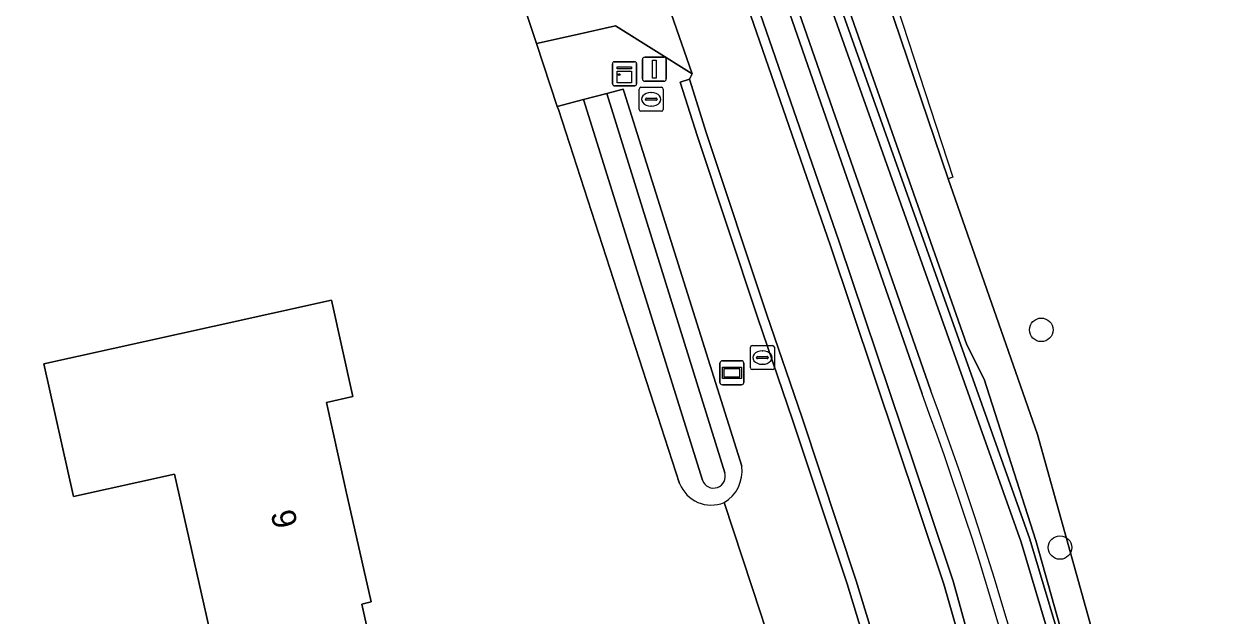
# Model space of a CAD drawing. Extents: x 162510 to 163918, y 388494 to 389774.
# Drawn here: x 163268.7 to 163318.9, y 389108.3 to 389132.9 of the extents above; entities that cross this region are included whole.
import ezdxf

# ---------------------------------------------------------------- set-up
doc = ezdxf.new("R2010")
doc.units = 0
for name, color, linetype in [('IMGEO_Afsluitpaal', 7, 'Continuous'), ('IMGEO_Boom', 7, 'Continuous'), ('IMGEO_Brandkraan', 7, 'Continuous'), ('IMGEO_Erf', 7, 'Continuous'), ('IMGEO_Grasland_agrarisch', 7, 'Continuous'), ('IMGEO_Grasland_overig', 7, 'Continuous'), ('IMGEO_Groenvoorziening', 7, 'Continuous'), ('IMGEO_Hek', 7, 'Continuous'), ('IMGEO_Kast', 7, 'Continuous'), ('IMGEO_Loofbos', 7, 'Continuous'), ('IMGEO_Oever', 7, 'Continuous'), ('IMGEO_Pand', 7, 'Continuous'), ('IMGEO_Pand_nummerreeks', 7, 'Continuous'), ('IMGEO_Rijbaan_lokaal_gesloten', 7, 'Continuous'), ('IMGEO_Rijbaan_lokaal_halfverhard', 7, 'Continuous'), ('IMGEO_Rijbaan_lokaal_open', 7, 'Continuous'), ('IMGEO_Rioolput', 7, 'Continuous'), ('IMGEO_Verklikker', 7, 'Continuous'), ('IMGEO_Waterloop', 7, 'Continuous')]:
    doc.layers.add(name, color=color, linetype=linetype)

msp = doc.modelspace()

# ---------------------------------------------------------------- linework, layer by layer
at = {"layer": 'IMGEO_Afsluitpaal'}
for p, q in [((163294.442, 389130.657), (163294.442, 389131.457)), ((163294.442, 389131.457), (163294.442, 389130.657)), ((163294.542, 389131.557), (163295.332, 389131.557)), ((163295.332, 389131.557), (163294.542, 389131.557)), ((163295.432, 389131.457), (163295.432, 389130.657)), ((163295.432, 389130.657), (163295.432, 389131.457)), ((163295.332, 389130.557), (163294.542, 389130.557)), ((163294.542, 389130.557), (163295.332, 389130.557))]:
    msp.add_line(p, q, dxfattribs=at)
msp.add_lwpolyline([(163294.862, 389131.432), (163295.012, 389131.432), (163295.012, 389130.682), (163294.862, 389130.682), (163294.862, 389131.432)], dxfattribs=at)
for centre, start, end in [((163294.542, 389131.457), 90, 180), ((163294.542, 389131.457), 90, 180), ((163295.332, 389131.457), 0, 90), ((163295.332, 389131.457), 360, 90), ((163294.542, 389130.657), 180, 270), ((163294.542, 389130.657), 180, 270), ((163295.332, 389130.657), 270, 0), ((163295.332, 389130.657), 270, 0)]:
    msp.add_arc(centre, 0.1, start, end, dxfattribs=at)
at = {"layer": 'IMGEO_Boom'}
for centre in [(163311.036, 389120.214), (163311.815, 389111.157)]:
    msp.add_circle(centre, 0.489, dxfattribs=at)
at = {"layer": 'IMGEO_Brandkraan'}
for p, q in [((163298.932, 389118.636), (163298.932, 389119.488)), ((163299.007, 389119.562), (163299.859, 389119.562)), ((163299.234, 389119.105), (163299.632, 389119.105)), ((163299.42, 389119.342), (163299.445, 389119.342)), ((163299.933, 389119.488), (163299.933, 389118.636)), ((163299.191, 389119.056), (163299.191, 389119.068)), ((163299.629, 389119.019), (163299.231, 389119.019)), ((163299.443, 389118.782), (163299.418, 389118.782)), ((163299.675, 389119.068), (163299.675, 389119.056)), ((163299.859, 389118.562), (163299.007, 389118.562))]:
    msp.add_line(p, q, dxfattribs=at)
for points in [[(163298.932, 389118.636), (163298.932, 389119.488)], [(163299.007, 389119.562), (163299.859, 389119.562)], [(163299.933, 389119.488), (163299.933, 389118.636)], [(163299.859, 389118.562), (163299.007, 389118.562)]]:
    msp.add_lwpolyline(points, dxfattribs=at)
for centre, radius, start, end in [((163299.009, 389119.486), 0.0765, 91.552, 178.448), ((163299.009, 389119.486), 0.0765, 91.552, 178.448), ((163299.231, 389119.065), 0.0403, 85.8775, 175.7526), ((163299.636, 389119.067), 0.0386, 1.7309, 96.639), ((163299.857, 389119.486), 0.0765, 1.552, 88.448), ((163299.857, 389119.486), 0.0765, 1.552, 88.448), ((163299.009, 389118.638), 0.0765, 181.552, 268.448), ((163299.009, 389118.638), 0.0765, 181.552, 268.448), ((163299.228, 389119.055), 0.0366, 178.938, 274.7102), ((163299.632, 389119.062), 0.043, 264.8664, 352.4533), ((163299.857, 389118.638), 0.0765, 271.552, 358.448), ((163299.857, 389118.638), 0.0765, 271.552, 358.448)]:
    msp.add_arc(centre, radius, start, end, dxfattribs=at)
for centre, major_axis, ratio, start_param, end_param in [((163299.419, 389119.062), (-0.387, 0.002), 0.722429, 4.712389, 7.853982), ((163299.444, 389119.062), (-0.39, 0.002), 0.717154, 1.570796, 4.712389)]:
    msp.add_ellipse(centre, major_axis=major_axis, ratio=ratio, start_param=start_param, end_param=end_param, dxfattribs=at)
at = {"layer": 'IMGEO_Erf'}
msp.add_lwpolyline([(163295.99, 389113.816), (163290.943, 389129.375), (163290.899, 389129.508), (163290.029, 389132.125), (163288.773, 389135.907), (163287.617, 389139.385), (163285.544, 389145.627), (163261.78, 389139.826), (163241.096, 389135.563), (163217.196, 389130.559), (163224.258, 389085.897), (163224.403, 389084.979), (163231.973, 389086.773), (163247.896, 389090.8), (163281.65, 389099.338), (163299.098, 389104.325), (163298.18, 389106.706), (163299.751, 389107.167), (163299.514, 389107.922), (163299.362, 389108.405), (163297.837, 389113.028)], dxfattribs=at)
msp.add_lwpolyline([(163269.539, 389118.803), (163276.624, 389120.373), (163281.505, 389121.454), (163282.389, 389117.439), (163281.296, 389117.198), (163282.056, 389113.745), (163282.1, 389113.551), (163283.16, 389108.904), (163282.762, 389108.795), (163282.963, 389107.934), (163278.843, 389107.021), (163278.657, 389107.864), (163276.508, 389107.388), (163274.968, 389114.211), (163270.766, 389113.282)], close=True, dxfattribs=at)
msp.add_arc((163297.304, 389114.337), 1.413, 201.6231, 292.1671, dxfattribs=at)
at = {"layer": 'IMGEO_Grasland_agrarisch'}
for points in [[(163307.161, 389126.5), (163310.878, 389115.861), (163314.091, 389104.329), (163316.991, 389092.126), (163318.506, 389073.312), (163367.516, 389078.302), (163374.787, 389079.284), (163366.654, 389123.96), (163359.915, 389160.853), (163356.398, 389163.04), (163342.099, 389172.967), (163307.356, 389168.666), (163293.477, 389168.592), (163298.963, 389150.69)], [(163359.915, 389160.853), (163356.398, 389163.04), (163342.099, 389172.967), (163307.356, 389168.666), (163293.81, 389168.694), (163295.529, 389162.768), (163307.351, 389126.562), (163307.161, 389126.5), (163310.878, 389115.861), (163314.091, 389104.329), (163316.991, 389092.126), (163318.506, 389073.312), (163367.516, 389078.302), (163374.787, 389079.284), (163366.654, 389123.96)]]:
    msp.add_lwpolyline(points, close=True, dxfattribs=at)
at = {"layer": 'IMGEO_Grasland_overig'}
for points in [[(163269.586, 389223.92), (163270.524, 389220.606), (163272.482, 389214.36), (163274.556, 389207.832), (163276.596, 389201.21), (163279.233, 389192.779), (163282.821, 389181.85), (163285.014, 389175.274), (163289.738, 389161.323), (163294.443, 389147.5), (163296.944, 389140.288), (163298.713, 389135.186), (163302.632, 389123.878), (163306.31, 389112.906), (163307.368, 389109.754), (163307.917, 389107.807), (163308.741, 389104.905), (163309.765, 389101.198)], [(163380.603, 389076.405), (163382.808, 389076.715), (163383.644, 389076.959), (163385.385, 389077.656), (163386.687, 389078.319), (163386.481, 389080.864), (163374.787, 389079.284), (163367.516, 389078.302), (163318.506, 389073.312), (163316.991, 389092.126), (163314.091, 389104.329), (163310.878, 389115.861), (163307.161, 389126.5), (163298.963, 389150.69), (163293.477, 389168.592), (163291.787, 389174.109), (163289.599, 389172.956)], [(163289.599, 389172.956), (163289.702, 389172.575), (163290.669, 389168.7), (163291.377, 389166.688), (163307.934, 389119.584), (163308.654, 389118.16), (163310.816, 389111.455), (163312.329, 389106.026), (163313.789, 389100.576), (163315.665, 389092.463), (163317.148, 389071.288), (163317.163, 389071.036), (163328.39, 389071.628), (163350.586, 389073.126), (163366.024, 389074.655), (163372.103, 389075.6), (163375.233, 389076.384), (163378.482, 389077.444), (163380.722, 389078.49), (163381.482, 389078.62), (163381.768, 389078.515), (163381.923, 389078.247), (163381.855, 389077.888)], [(163306.075, 389117.546), (163291.361, 389159.819)]]:
    msp.add_lwpolyline(points, dxfattribs=at)
msp.add_arc((163166.83, 389065.927), 148.505, 9.06284, 20.34014, dxfattribs=at)
at = {"layer": 'IMGEO_Groenvoorziening'}
msp.add_lwpolyline([(163289.599, 389172.956), (163288.407, 389172.464), (163292.024, 389161.132), (163292.522, 389161.166), (163292.978, 389160.963), (163310.563, 389111.499), (163312.208, 389105.99), (163312.329, 389106.026), (163310.816, 389111.455), (163308.654, 389118.16), (163307.934, 389119.584), (163291.377, 389166.688), (163290.669, 389168.7), (163289.702, 389172.575)], close=True, dxfattribs=at)
at = {"layer": 'IMGEO_Hek'}
for points in [[(163291.787, 389174.109), (163293.477, 389168.592), (163298.963, 389150.69), (163307.161, 389126.5)], [(163386.481, 389080.864), (163374.787, 389079.284), (163367.516, 389078.302), (163318.506, 389073.312), (163316.991, 389092.126), (163314.091, 389104.329), (163310.878, 389115.861), (163307.161, 389126.5)]]:
    msp.add_lwpolyline(points, dxfattribs=at)
at = {"layer": 'IMGEO_Kast'}
for p, q in [((163293.197, 389130.442), (163293.197, 389131.283)), ((163293.197, 389131.283), (163293.197, 389130.442)), ((163293.272, 389131.367), (163294.113, 389131.367)), ((163294.113, 389131.367), (163293.272, 389131.367)), ((163294.197, 389131.292), (163294.197, 389130.451)), ((163294.197, 389130.451), (163294.197, 389131.292)), ((163294.122, 389130.367), (163293.281, 389130.367)), ((163293.281, 389130.367), (163294.122, 389130.367))]:
    msp.add_line(p, q, dxfattribs=at)
for points in [[(163293.392, 389131.157), (163293.992, 389131.157), (163293.992, 389131.072), (163293.392, 389131.072), (163293.392, 389131.157)], [(163293.392, 389130.982), (163293.992, 389130.982), (163293.992, 389130.493), (163293.392, 389130.493), (163293.392, 389130.982)]]:
    msp.add_lwpolyline(points, dxfattribs=at)
msp.add_circle((163293.476, 389130.831), 0.0377, dxfattribs=at)
for centre, start, end in [((163293.275, 389131.289), 92.4484, 184.2845), ((163293.275, 389131.289), 92.4484, 184.2845), ((163294.119, 389131.289), 2.4484, 94.2845), ((163294.119, 389131.289), 2.4484, 94.2845), ((163293.275, 389130.445), 182.4484, 274.2845), ((163293.275, 389130.445), 182.4484, 274.2845), ((163294.119, 389130.445), 272.4484, 4.2845), ((163294.119, 389130.445), 272.4484, 4.2845)]:
    msp.add_arc(centre, 0.0779, start, end, dxfattribs=at)
at = {"layer": 'IMGEO_Loofbos'}
for points in [[(163304.458, 389104.718), (163302.957, 389109.643), (163300.704, 389116.431), (163299.226, 389120.745), (163296.729, 389128.263), (163296.018, 389130.522), (163296.4, 389130.642), (163296.508, 389130.868), (163293.321, 389132.857), (163291.728, 389132.494), (163290.029, 389132.125), (163290.899, 389129.508), (163291.995, 389129.793), (163292.964, 389130.045), (163293.639, 389130.221), (163293.675, 389130.106), (163298.577, 389114.536)], [(163297.837, 389113.028), (163299.362, 389108.405), (163299.514, 389107.922), (163299.751, 389107.167), (163299.799, 389107.183), (163299.874, 389107.207), (163300.332, 389107.355), (163301.202, 389107.649), (163302.376, 389104.587), (163303.586, 389100.712), (163305.385, 389094.695), (163306.866, 389087.58), (163307.505, 389083.14), (163307.628, 389080.974), (163307.534, 389078.67), (163306.948, 389074.273), (163306.179, 389070.481), (163304.839, 389066.018), (163303.89, 389063.876), (163301.226, 389059.667), (163296.877, 389054.754), (163292.823, 389050.667), (163286.398, 389045.174), (163271.935, 389034.148)]]:
    msp.add_lwpolyline(points, dxfattribs=at)
msp.add_arc((163297.053, 389114.348), 1.536, 300.7033, 7.0208, dxfattribs=at)
at = {"layer": 'IMGEO_Oever'}
for points in [[(163312.208, 389105.99), (163310.563, 389111.499), (163292.978, 389160.963)], [(163292.669, 389160.677), (163310.195, 389111.379), (163311.834, 389105.891)], [(163291.361, 389159.819), (163306.075, 389117.546)], [(163306.442, 389117.671), (163291.732, 389159.93)], [(163293.675, 389130.106), (163293.639, 389130.221), (163292.964, 389130.045), (163297.867, 389114.272)], [(163296.943, 389113.959), (163291.995, 389129.793), (163290.899, 389129.508), (163290.943, 389129.375), (163295.99, 389113.816)], [(163298.577, 389114.536), (163293.675, 389130.106)]]:
    msp.add_lwpolyline(points, dxfattribs=at)
for centre, radius, start, end in [((163166.761, 389065.905), 148.965, 9.06066, 20.33478), ((163166.83, 389065.927), 148.505, 9.06284, 20.34014), ((163297.404, 389114.119), 0.488, 199.0918, 18.3353), ((163297.053, 389114.348), 1.536, 300.7033, 7.0208), ((163297.304, 389114.337), 1.413, 201.6231, 292.1671)]:
    msp.add_arc(centre, radius, start, end, dxfattribs=at)
at = {"layer": 'IMGEO_Pand'}
msp.add_lwpolyline([(163282.389, 389117.439), (163281.505, 389121.454), (163276.624, 389120.373), (163269.539, 389118.803), (163270.766, 389113.282), (163274.968, 389114.211), (163276.508, 389107.388), (163278.657, 389107.864), (163278.843, 389107.021), (163282.963, 389107.934), (163282.762, 389108.795), (163283.16, 389108.904), (163282.1, 389113.551), (163282.056, 389113.745), (163281.296, 389117.198)], close=True, dxfattribs=at)
at = {"layer": 'IMGEO_Rijbaan_lokaal_gesloten'}
msp.add_lwpolyline([(163309.376, 389101.103), (163308.355, 389104.798), (163307.532, 389107.698), (163306.989, 389109.627), (163305.931, 389112.779), (163302.253, 389123.751), (163298.335, 389135.055), (163296.565, 389140.159), (163293.622, 389139.158), (163293.616, 389139.157), (163294.764, 389135.9), (163296.508, 389130.868), (163296.4, 389130.642), (163297.109, 389128.389), (163299.604, 389120.875), (163301.084, 389116.557), (163303.337, 389109.769), (163304.842, 389104.831)], dxfattribs=at)
at = {"layer": 'IMGEO_Rijbaan_lokaal_halfverhard'}
for points in [[(163296.944, 389140.288), (163296.565, 389140.159), (163298.335, 389135.055), (163302.253, 389123.751), (163305.931, 389112.779), (163306.989, 389109.627), (163307.532, 389107.698), (163308.355, 389104.798), (163309.376, 389101.103)], [(163309.765, 389101.198), (163308.741, 389104.905), (163307.917, 389107.807), (163307.368, 389109.754), (163306.31, 389112.906), (163302.632, 389123.878), (163298.713, 389135.186), (163296.944, 389140.288)], [(163296.4, 389130.642), (163296.018, 389130.522), (163296.729, 389128.263), (163299.226, 389120.745), (163300.704, 389116.431), (163302.957, 389109.643), (163304.458, 389104.718)], [(163304.842, 389104.831), (163303.337, 389109.769), (163301.084, 389116.557), (163299.604, 389120.875), (163297.109, 389128.389), (163296.4, 389130.642)]]:
    msp.add_lwpolyline(points, dxfattribs=at)
at = {"layer": 'IMGEO_Rijbaan_lokaal_open'}
msp.add_lwpolyline([(163293.616, 389139.157), (163293.612, 389139.167), (163293.417, 389139.208), (163291.924, 389136.772), (163290.449, 389136.423), (163288.773, 389135.907), (163290.029, 389132.125), (163291.728, 389132.494), (163293.321, 389132.857), (163296.508, 389130.868), (163294.764, 389135.9)], close=True, dxfattribs=at)
at = {"layer": 'IMGEO_Rioolput'}
for p, q in [((163294.306, 389129.379), (163294.306, 389130.231)), ((163294.381, 389130.305), (163295.233, 389130.305)), ((163295.307, 389130.231), (163295.307, 389129.379)), ((163294.565, 389129.799), (163294.565, 389129.811)), ((163295.003, 389129.762), (163294.605, 389129.762)), ((163294.608, 389129.848), (163295.006, 389129.848)), ((163294.794, 389130.085), (163294.819, 389130.085)), ((163295.049, 389129.811), (163295.049, 389129.799)), ((163295.233, 389129.305), (163294.381, 389129.305)), ((163294.817, 389129.525), (163294.792, 389129.525))]:
    msp.add_line(p, q, dxfattribs=at)
for points in [[(163294.306, 389129.379), (163294.306, 389130.231)], [(163294.381, 389130.305), (163295.233, 389130.305)], [(163295.307, 389130.231), (163295.307, 389129.379)], [(163295.233, 389129.305), (163294.381, 389129.305)]]:
    msp.add_lwpolyline(points, dxfattribs=at)
for centre, radius, start, end in [((163294.383, 389130.229), 0.0765, 91.552, 178.448), ((163294.383, 389130.229), 0.0765, 91.552, 178.448), ((163295.231, 389130.229), 0.0765, 1.552, 88.448), ((163295.231, 389130.229), 0.0765, 1.552, 88.448), ((163294.605, 389129.808), 0.0403, 85.8775, 175.7526), ((163294.602, 389129.798), 0.0366, 178.938, 274.7102), ((163295.006, 389129.805), 0.043, 264.8664, 352.4533), ((163295.01, 389129.81), 0.0386, 1.7309, 96.639), ((163294.383, 389129.381), 0.0765, 181.552, 268.448), ((163294.383, 389129.381), 0.0765, 181.552, 268.448), ((163295.231, 389129.381), 0.0765, 271.552, 358.448), ((163295.231, 389129.381), 0.0765, 271.552, 358.448)]:
    msp.add_arc(centre, radius, start, end, dxfattribs=at)
for centre, major_axis, ratio, start_param, end_param in [((163294.793, 389129.805), (-0.387, 0.002), 0.722429, 4.712389, 7.853982), ((163294.818, 389129.805), (-0.39, 0.002), 0.717154, 1.570796, 4.712389)]:
    msp.add_ellipse(centre, major_axis=major_axis, ratio=ratio, start_param=start_param, end_param=end_param, dxfattribs=at)
at = {"layer": 'IMGEO_Verklikker'}
for p, q in [((163297.668, 389118.026), (163297.668, 389118.826)), ((163297.668, 389118.826), (163297.668, 389118.026)), ((163297.768, 389118.926), (163298.558, 389118.926)), ((163298.558, 389118.926), (163297.768, 389118.926)), ((163298.658, 389118.826), (163298.658, 389118.026)), ((163298.658, 389118.026), (163298.658, 389118.826)), ((163298.558, 389117.926), (163297.768, 389117.926)), ((163297.768, 389117.926), (163298.558, 389117.926))]:
    msp.add_line(p, q, dxfattribs=at)
for points in [[(163297.769, 389118.658), (163298.557, 389118.658), (163298.557, 389118.194), (163297.769, 389118.194), (163297.769, 389118.658)], [(163297.834, 389118.593), (163297.834, 389118.259), (163298.492, 389118.259), (163298.492, 389118.593), (163297.834, 389118.593)]]:
    msp.add_lwpolyline(points, dxfattribs=at)
for centre, start, end in [((163297.768, 389118.826), 90, 180), ((163297.768, 389118.826), 90, 180), ((163298.558, 389118.826), 0, 90), ((163298.558, 389118.826), 360, 90), ((163297.768, 389118.026), 180, 270), ((163297.768, 389118.026), 180, 270), ((163298.558, 389118.026), 270, 0), ((163298.558, 389118.026), 270, 0)]:
    msp.add_arc(centre, 0.1, start, end, dxfattribs=at)
at = {"layer": 'IMGEO_Waterloop'}
for points in [[(163311.834, 389105.891), (163310.195, 389111.379), (163292.669, 389160.677)], [(163291.732, 389159.93), (163306.442, 389117.671)], [(163292.964, 389130.045), (163291.995, 389129.793), (163296.943, 389113.959)], [(163297.867, 389114.272), (163292.964, 389130.045)]]:
    msp.add_lwpolyline(points, dxfattribs=at)
for centre, radius, start, end in [((163166.761, 389065.905), 148.965, 9.06066, 20.33478), ((163297.404, 389114.119), 0.488, 199.0918, 18.3353)]:
    msp.add_arc(centre, radius, start, end, dxfattribs=at)

# ---------------------------------------------------------------- texts
at = {"layer": 'IMGEO_Pand_nummerreeks'}
msp.add_text('9', height=1, rotation=282.6662, dxfattribs=at).set_placement((163278.967, 389112.6))

doc.saveas('drawing.dxf')
